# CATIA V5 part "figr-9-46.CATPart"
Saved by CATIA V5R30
Part number: Part1
Bounding box of the stored display mesh (mm): x -159.661 to 182.627, y -78.048 to 78.048, z 0 to 72.429
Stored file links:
  D:\PROJECTS\CATIA V56R 2020\Resources\Parts File\c09_catia_v5_6r2020_prt\figr-9-46.CATPart
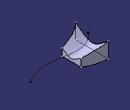
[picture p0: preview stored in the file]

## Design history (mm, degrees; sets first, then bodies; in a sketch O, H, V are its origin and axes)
Body1 (main body)
  Plane1: type Offset, RefPlane yz-plane, Offset 100
  Plane2: type Offset, RefPlane yz-plane, Offset 100, reversed
  Sketch1 on Plane1, origin (100, 0, 0), H (0, 1, 0), V (0, 0, 1)
    point P1 (0, 15.965)
    hyperbola C1
    point P2 (0, 3.0416)
    line L1 (54.8261, 44.8858) -> (54.8261, 0)
    point P5 (54.8261, 0)
    line L2 (-54.8261, 44.8858) -> (-54.8261, 0)
    point P6 (-54.8261, 0)
    line L3 (-54.8261, 0) -> (54.8261, 0)
    coincidence: P1 V, P2 V, P5 H, P6 H
    vertical: L1 V, L2 V
    horizontal: L3 H
  Sketch2 on xy-plane, origin (0, 0, 0), H (1, 0, 0), V (0, 1, 0)
    spline S1 through (-159.6608, -77.1468) (-77.8466, -31.8169) (23.6283, -41.4968) (182.6271, -11.7333)
  Sketch3 on yz-plane, origin (0, 0, 0), H (0, 1, 0), V (0, 0, 1)
    point P1 (0, 18.9787)
    hyperbola C1
    point P2 (0, 2.6681)
    line L1 (48.2237, 37.1764) -> (48.2237, 0)
    point P5 (48.2237, 0)
    line L2 (-43.6563, 34.1546) -> (-43.6563, 0)
    point P6 (-43.6563, 0)
    line L3 (-43.6563, 0) -> (48.2237, 0)
    coincidence: P1 V, P2 V, P5 H, P6 H
    vertical: L1 V, L2 V
    horizontal: L3 H
  Sketch4 on Plane2, origin (-100, 0, 0), H (0, 1, 0), V (0, 0, 1)
    point P1 (0, 140.6052)
    point P2 (0, 41.8972)
    hyperbola C1
    line L1 (78.0478, 72.4293) -> (78.0478, 0)
    point P5 (78.0478, 0)
    line L2 (-78.0478, 72.4293) -> (-78.0478, 0)
    point P6 (-78.0478, 0)
    line L3 (-78.0478, 0) -> (78.0478, 0)
    coincidence: P1 V, P2 V, P5 H, P6 H
    vertical: L1 V, L2 V
    horizontal: L3 H
  Loft1: solid, Sections (Sketch3; Sketch4), Spine Sketch2
  Loft2: solid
